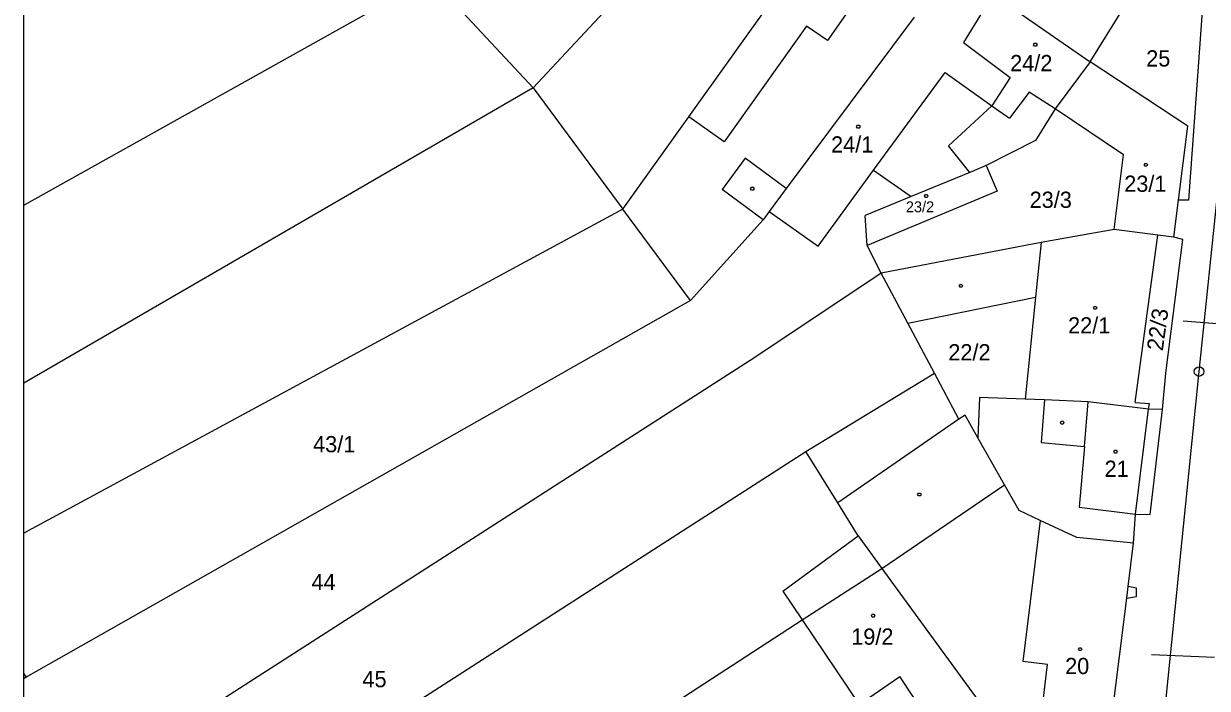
# Model space of a CAD drawing. Extents: x -639621 to -639329, y -1192893 to -1192488.
# Drawn here: x -639621.3 to -639497.3, y -1192813.4 to -1192743.8 of the extents above; entities that cross this region are included whole.
import ezdxf

# ---------------------------------------------------------------- set-up
doc = ezdxf.new("R2010")
doc.units = 0
for name, color, linetype in [('Vrstva 1', 7, 'Continuous'), ('Vrstva 19', 7, 'Continuous'), ('Vrstva 2', 7, 'Continuous'), ('Vrstva 25', 7, 'Continuous'), ('Vrstva 4', 7, 'Continuous'), ('Vrstva 5', 7, 'Continuous'), ('Vrstva 61', 7, 'Continuous')]:
    doc.layers.add(name, color=color, linetype=linetype)

msp = doc.modelspace()

# ---------------------------------------------------------------- linework, layer by layer
at = {"layer": 'Vrstva 1'}
for p, q in [((-639509.52, -1192747.76), (-639501.41, -1192734.7)), ((-639551.56, -1192753.52), (-639538.8, -1192735.67)), ((-639497.4, -1192737.18), (-639499.22, -1192762.27)), ((-639621.26, -1192762.78), (-639578.63, -1192738.96)), ((-639578.63, -1192738.96), (-639567.88, -1192750.5)), ((-639558.48, -1192740.42), (-639567.88, -1192750.5)), ((-639519.72, -1192740.7), (-639522.79, -1192745.74)), ((-639519.51, -1192740.84), (-639509.52, -1192747.76)), ((-639527.96, -1192743.09), (-639541.39, -1192761.03)), ((-639522.79, -1192745.74), (-639517.92, -1192749.42)), ((-639509.52, -1192747.76), (-639513.18, -1192752.69)), ((-639499.31, -1192754.5), (-639509.52, -1192747.76)), ((-639567.88, -1192750.5), (-639621.26, -1192781.4)), ((-639567.88, -1192750.5), (-639558.48, -1192763.2)), ((-639517.92, -1192749.42), (-639519.82, -1192752.36)), ((-639519.82, -1192752.36), (-639524.38, -1192756.57)), ((-639513.18, -1192752.69), (-639515.24, -1192756.01)), ((-639506.05, -1192757.52), (-639513.18, -1192752.69)), ((-639558.48, -1192763.2), (-639551.56, -1192753.52)), ((-639500.28, -1192762.25), (-639499.31, -1192754.5)), ((-639522.14, -1192759.34), (-639524.38, -1192756.57)), ((-639515.24, -1192756.01), (-639520.41, -1192758.62)), ((-639507.01, -1192765.32), (-639506.05, -1192757.52)), ((-639538.04, -1192767.06), (-639532.22, -1192759.12)), ((-639532.22, -1192759.12), (-639528.29, -1192761.88)), ((-639520.41, -1192758.62), (-639522.14, -1192759.34)), ((-639520.41, -1192758.62), (-639519.26, -1192761.3)), ((-639522.14, -1192759.34), (-639528.29, -1192761.88)), ((-639541.39, -1192761.03), (-639543.16, -1192763.44)), ((-639519.26, -1192761.3), (-639532.89, -1192767.01)), ((-639528.29, -1192761.88), (-639533.09, -1192763.87)), ((-639500.77, -1192766.13), (-639500.28, -1192762.25)), ((-639499.22, -1192762.27), (-639500.28, -1192762.25)), ((-639558.48, -1192763.2), (-639621.26, -1192797.12)), ((-639551.4, -1192772.76), (-639558.48, -1192763.2)), ((-639543.16, -1192763.44), (-639543.8, -1192764.31)), ((-639543.16, -1192763.44), (-639538.04, -1192767.06)), ((-639532.89, -1192767.01), (-639533.09, -1192763.87)), ((-639543.8, -1192764.31), (-639551.4, -1192772.76)), ((-639507.01, -1192765.32), (-639514.66, -1192766.67)), ((-639502.43, -1192765.91), (-639507.01, -1192765.32)), ((-639514.66, -1192766.67), (-639531.42, -1192769.91)), ((-639504.82, -1192783.44), (-639502.43, -1192765.91)), ((-639500.77, -1192766.13), (-639502.43, -1192765.91)), ((-639501.61, -1192780.38), (-639499.83, -1192766.37)), ((-639499.83, -1192766.37), (-639500.77, -1192766.13)), ((-639531.42, -1192769.91), (-639532.89, -1192767.01)), ((-639531.42, -1192769.91), (-639544.66, -1192778.72)), ((-639528.64, -1192775.13), (-639531.42, -1192769.91)), ((-639551.4, -1192772.76), (-639621, -1192812.21)), ((-639528.64, -1192775.13), (-639515.25, -1192772.42)), ((-639515.25, -1192772.42), (-639516.34, -1192783.09)), ((-639525.84, -1192780.38), (-639528.64, -1192775.13)), ((-639544.66, -1192778.72), (-639621.26, -1192827.88)), ((-639539.3, -1192788.57), (-639525.84, -1192780.38)), ((-639523.27, -1192785.19), (-639525.84, -1192780.38)), ((-639501.94, -1192784.17), (-639501.61, -1192780.38)), ((-639521.11, -1192782.9), (-639521.28, -1192787.13)), ((-639516.34, -1192783.09), (-639521.11, -1192782.9)), ((-639514.3, -1192783.17), (-639516.34, -1192783.09)), ((-639509.72, -1192783.36), (-639514.3, -1192783.17)), ((-639503.4, -1192784.15), (-639509.72, -1192783.36)), ((-639504.82, -1192783.44), (-639503.32, -1192783.54)), ((-639503.4, -1192784.15), (-639503.32, -1192783.54)), ((-639522.63, -1192784.75), (-639523.27, -1192785.19)), ((-639521.28, -1192787.13), (-639522.63, -1192784.75)), ((-639501.94, -1192784.17), (-639503.4, -1192784.15)), ((-639503.23, -1192795.15), (-639501.94, -1192784.17)), ((-639518.5, -1192792.05), (-639521.28, -1192787.13)), ((-639621.26, -1192841.23), (-639539.3, -1192788.57)), ((-639535.98, -1192793.95), (-639539.3, -1192788.57)), ((-639516.97, -1192794.76), (-639518.5, -1192792.05)), ((-639533.84, -1192797.4), (-639535.98, -1192793.95)), ((-639514.78, -1192795.78), (-639516.97, -1192794.76)), ((-639504.98, -1192798.18), (-639504.77, -1192795.13)), ((-639504.77, -1192795.13), (-639503.23, -1192795.15)), ((-639510.94, -1192797.57), (-639514.78, -1192795.78)), ((-639541.72, -1192803.2), (-639533.84, -1192797.4)), ((-639533.84, -1192797.4), (-639531.35, -1192800.82)), ((-639504.98, -1192798.18), (-639510.94, -1192797.57)), ((-639505.54, -1192802.7), (-639504.98, -1192798.18)), ((-639531.35, -1192800.82), (-639520.33, -1192815.94)), ((-639541.72, -1192803.2), (-639539.7, -1192806.21)), ((-639505.7, -1192803.94), (-639504.68, -1192803.75)), ((-639504.68, -1192802.89), (-639505.54, -1192802.7)), ((-639504.68, -1192803.75), (-639504.68, -1192802.89)), ((-639508.25, -1192824.43), (-639505.7, -1192803.94)), ((-639614.88, -1192854.94), (-639539.7, -1192806.21)), ((-639539.7, -1192806.21), (-639533.72, -1192815.06)), ((-639621.26, -1192811.84), (-639621, -1192812.21)), ((-639621, -1192812.21), (-639621.26, -1192812.36))]:
    msp.add_line(p, q, dxfattribs=at)
at = {"layer": 'Vrstva 19'}
msp.add_lwpolyline([(-639498.88, -1192834.04), (-639503.12, -1192829.95), (-639498.12, -1192780.2), (-639493.99, -1192740.51), (-639491, -1192720.22)], dxfattribs=at)
msp.add_circle((-639498.12, -1192780.2), 0.5, dxfattribs=at)
at = {"layer": 'Vrstva 25'}
for p, q in [((-639499.78, -1192774.9), (-639492.99, -1192775.4)), ((-639503.1, -1192809.83), (-639496.5, -1192810.09))]:
    msp.add_line(p, q, dxfattribs=at)
at = {"layer": 'Vrstva 4'}
for p, q in [((-639534.41, -1192741.81), (-639537.06, -1192745.52)), ((-639539.25, -1192744.04), (-639547.89, -1192756.14)), ((-639537.06, -1192745.52), (-639539.25, -1192744.04)), ((-639532.22, -1192759.12), (-639524.71, -1192748.9)), ((-639524.71, -1192748.9), (-639519.82, -1192752.36)), ((-639515.91, -1192750.96), (-639517.98, -1192753.67)), ((-639513.18, -1192752.69), (-639515.91, -1192750.96)), ((-639519.82, -1192752.36), (-639517.98, -1192753.67)), ((-639547.89, -1192756.14), (-639551.56, -1192753.52)), ((-639545.66, -1192757.87), (-639548.08, -1192761.14)), ((-639541.39, -1192761.03), (-639545.66, -1192757.87)), ((-639543.8, -1192764.31), (-639548.08, -1192761.14)), ((-639514.66, -1192766.67), (-639515.25, -1192772.42)), ((-639514.3, -1192783.17), (-639514.67, -1192787.64)), ((-639510.13, -1192788.03), (-639509.72, -1192783.36)), ((-639523.27, -1192785.19), (-639535.98, -1192793.95)), ((-639504.77, -1192795.13), (-639503.4, -1192784.15)), ((-639514.67, -1192787.64), (-639510.13, -1192788.03)), ((-639510.13, -1192788.03), (-639510.69, -1192794.39)), ((-639531.35, -1192800.82), (-639518.5, -1192792.05)), ((-639510.69, -1192794.39), (-639504.77, -1192795.13)), ((-639514.78, -1192795.78), (-639516.58, -1192810.54)), ((-639539.7, -1192806.21), (-639531.35, -1192800.82)), ((-639505.7, -1192803.94), (-639505.54, -1192802.7)), ((-639514, -1192810.86), (-639516.58, -1192810.54)), ((-639515.43, -1192822.65), (-639514, -1192810.86)), ((-639533.72, -1192815.06), (-639529.47, -1192812.12)), ((-639524.92, -1192818.97), (-639529.47, -1192812.12))]:
    msp.add_line(p, q, dxfattribs=at)
at = {"layer": 'Vrstva 5'}
for points in [[(-639515.18, -1192745.83), (-639515.09, -1192745.98), (-639515.18, -1192746.13), (-639515.36, -1192746.13), (-639515.45, -1192745.98), (-639515.36, -1192745.83)], [(-639533.73, -1192754.4), (-639533.64, -1192754.55), (-639533.73, -1192754.7), (-639533.91, -1192754.7), (-639534, -1192754.55), (-639533.91, -1192754.4)], [(-639503.6, -1192758.41), (-639503.51, -1192758.56), (-639503.6, -1192758.71), (-639503.78, -1192758.71), (-639503.87, -1192758.56), (-639503.78, -1192758.41)], [(-639544.83, -1192760.9), (-639544.74, -1192761.05), (-639544.83, -1192761.2), (-639545.01, -1192761.2), (-639545.1, -1192761.05), (-639545.01, -1192760.9)], [(-639526.61, -1192761.67), (-639526.52, -1192761.82), (-639526.61, -1192761.97), (-639526.79, -1192761.97), (-639526.88, -1192761.82), (-639526.79, -1192761.67)], [(-639522.98, -1192771.07), (-639522.89, -1192771.22), (-639522.98, -1192771.37), (-639523.16, -1192771.37), (-639523.25, -1192771.22), (-639523.16, -1192771.07)], [(-639508.91, -1192773.37), (-639508.82, -1192773.52), (-639508.91, -1192773.67), (-639509.09, -1192773.67), (-639509.18, -1192773.52), (-639509.09, -1192773.37)], [(-639512.37, -1192785.41), (-639512.28, -1192785.56), (-639512.37, -1192785.71), (-639512.55, -1192785.71), (-639512.64, -1192785.56), (-639512.55, -1192785.41)], [(-639506.79, -1192788.43), (-639506.7, -1192788.58), (-639506.79, -1192788.73), (-639506.97, -1192788.73), (-639507.06, -1192788.58), (-639506.97, -1192788.43)], [(-639527.34, -1192792.92), (-639527.25, -1192793.07), (-639527.34, -1192793.22), (-639527.52, -1192793.22), (-639527.61, -1192793.07), (-639527.52, -1192792.92)], [(-639532.18, -1192805.6), (-639532.09, -1192805.75), (-639532.18, -1192805.9), (-639532.36, -1192805.9), (-639532.45, -1192805.75), (-639532.36, -1192805.6)], [(-639510.48, -1192809.12), (-639510.39, -1192809.27), (-639510.48, -1192809.42), (-639510.66, -1192809.42), (-639510.75, -1192809.27), (-639510.66, -1192809.12)]]:
    msp.add_lwpolyline(points, close=True, dxfattribs=at)
at = {"layer": 'Vrstva 61'}
msp.add_lwpolyline([(-639621.26, -1192893.33), (-639621.26, -1192487.83)], dxfattribs=at)

# ---------------------------------------------------------------- texts
at = {"layer": 'Vrstva 2'}
for s, height, p in [('25', 1.7, (-639503.66, -1192748.26)), ('24/2', 1.7, (-639517.91, -1192748.75)), ('24/1', 1.7, (-639536.67, -1192757.27)), ('23/1', 1.7, (-639505.96, -1192761.38)), ('23/3', 1.7, (-639515.87, -1192763.06)), ('23/2', 1.14, (-639528.84, -1192763.52)), ('22/1', 1.7, (-639511.84, -1192776.21)), ('22/2', 1.7, (-639524.39, -1192779.03)), ('43/1', 1.7, (-639590.94, -1192788.65)), ('21', 1.7, (-639508.02, -1192791.23)), ('44', 1.7, (-639591.11, -1192803.08)), ('19/2', 1.7, (-639534.56, -1192808.8)), ('20', 1.7, (-639512.15, -1192811.88)), ('45', 1.7, (-639585.77, -1192813.25))]:
    msp.add_text(s, height=height, dxfattribs=at).set_placement(p)
msp.add_text('22/3', height=1.7, rotation=82.1049, dxfattribs=at).set_placement((-639501.92, -1192778.1))

doc.saveas('drawing.dxf')
